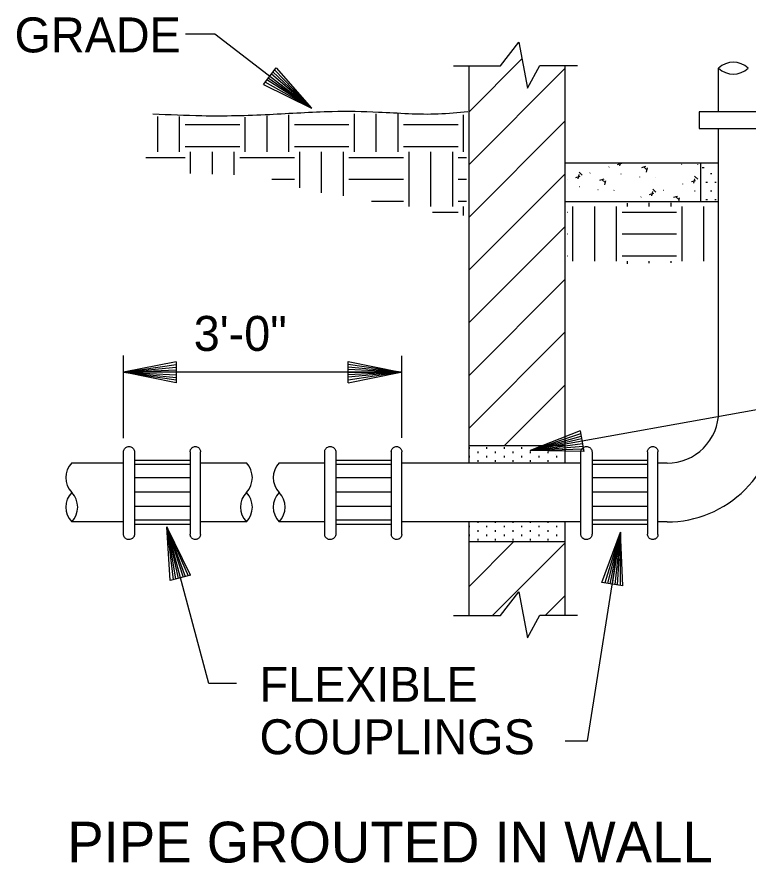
# Model space of a CAD drawing. Extents: x 9999.96 to 10005.26, y 9999.88 to 10002.38.
# Drawn here: x 10000.7094 to 10000.9186, y 10000.3471 to 10000.5891 of the extents above; entities that cross this region are included whole.
import ezdxf

# ---------------------------------------------------------------- set-up
doc = ezdxf.new("R2010")
doc.units = 0
doc.layers.add('Level 2', color=7, linetype='Continuous')

msp = doc.modelspace()

# ---------------------------------------------------------------- linework, layer by layer
at = {"layer": 'Level 2'}
for p, q in [((10000.83873, 10000.56198), (10000.85386, 10000.57711)), ((10000.77992, 10000.56982), (10000.78359, 10000.5746)), ((10000.78359, 10000.5746), (10000.79369, 10000.56304)), ((10000.83873, 10000.46147), (10000.83873, 10000.57519)), ((10000.86617, 10000.57519), (10000.86617, 10000.46147)), ((10000.78172, 10000.5722), (10000.79369, 10000.56304)), ((10000.79369, 10000.56304), (10000.78219, 10000.57279)), ((10000.79369, 10000.56304), (10000.78264, 10000.57339)), ((10000.79369, 10000.56304), (10000.78308, 10000.57396)), ((10000.83874, 10000.5469), (10000.86617, 10000.57433)), ((10000.91013, 10000.562), (10000.91013, 10000.57445)), ((10000.77992, 10000.56982), (10000.79369, 10000.56304)), ((10000.79369, 10000.56304), (10000.78039, 10000.57044)), ((10000.79369, 10000.56304), (10000.78088, 10000.57111)), ((10000.79369, 10000.56304), (10000.7813, 10000.57164)), ((10000.74969, 10000.55049), (10000.74969, 10000.56063)), ((10000.75594, 10000.55049), (10000.75594, 10000.56063)), ((10000.77469, 10000.55049), (10000.77469, 10000.56046)), ((10000.78094, 10000.55049), (10000.78094, 10000.56078)), ((10000.78719, 10000.55049), (10000.78719, 10000.56109)), ((10000.80594, 10000.55049), (10000.80594, 10000.5614)), ((10000.81219, 10000.55049), (10000.81219, 10000.56142)), ((10000.81844, 10000.55049), (10000.81844, 10000.56152)), ((10000.83719, 10000.55049), (10000.83719, 10000.56115)), ((10000.7575, 10000.5583), (10000.77313, 10000.5583)), ((10000.78875, 10000.5583), (10000.80438, 10000.5583)), ((10000.82, 10000.5583), (10000.83563, 10000.5583)), ((10000.83874, 10000.53181), (10000.86617, 10000.55925)), ((10000.91013, 10000.47621), (10000.91013, 10000.55723)), ((10000.7575, 10000.55205), (10000.77313, 10000.55205)), ((10000.75906, 10000.54436), (10000.75906, 10000.55049)), ((10000.76531, 10000.54418), (10000.76531, 10000.55049)), ((10000.77156, 10000.54398), (10000.77156, 10000.55049)), ((10000.78875, 10000.55205), (10000.80438, 10000.55205)), ((10000.79031, 10000.54022), (10000.79031, 10000.55049)), ((10000.79656, 10000.53875), (10000.79656, 10000.55049)), ((10000.80281, 10000.5379), (10000.80281, 10000.55049)), ((10000.82, 10000.55205), (10000.83563, 10000.55205)), ((10000.82156, 10000.53486), (10000.82156, 10000.55049)), ((10000.82781, 10000.53486), (10000.82781, 10000.55049)), ((10000.83406, 10000.53486), (10000.83406, 10000.55049)), ((10000.74622, 10000.54893), (10000.7575, 10000.54893)), ((10000.77313, 10000.54893), (10000.78875, 10000.54893)), ((10000.80438, 10000.54893), (10000.82, 10000.54893)), ((10000.83563, 10000.54893), (10000.838, 10000.54893)), ((10000.91017, 10000.54729), (10000.86617, 10000.54729)), ((10000.87876, 10000.54611), (10000.87878, 10000.54622)), ((10000.88124, 10000.54689), (10000.88244, 10000.54725)), ((10000.882, 10000.54729), (10000.88181, 10000.54648)), ((10000.88926, 10000.54631), (10000.88806, 10000.54595)), ((10000.8887, 10000.54624), (10000.8896, 10000.5454)), ((10000.88955, 10000.5447), (10000.88983, 10000.54592)), ((10000.89959, 10000.54694), (10000.89952, 10000.54701)), ((10000.90414, 10000.54689), (10000.90411, 10000.54678)), ((10000.90498, 10000.54729), (10000.90498, 10000.53632)), ((10000.90543, 10000.54608), (10000.90597, 10000.54608)), ((10000.83874, 10000.51674), (10000.86617, 10000.54417)), ((10000.86929, 10000.54323), (10000.87048, 10000.54359)), ((10000.87013, 10000.54404), (10000.86984, 10000.54283)), ((10000.8711, 10000.54389), (10000.8702, 10000.54473)), ((10000.87327, 10000.54445), (10000.8734, 10000.54448)), ((10000.88228, 10000.54418), (10000.88219, 10000.54415)), ((10000.88764, 10000.54328), (10000.88756, 10000.54335)), ((10000.89218, 10000.54323), (10000.89216, 10000.54314)), ((10000.90417, 10000.54268), (10000.90325, 10000.54353)), ((10000.90777, 10000.54436), (10000.90819, 10000.54436)), ((10000.78233, 10000.54268), (10000.78875, 10000.54268)), ((10000.80438, 10000.54268), (10000.82, 10000.54268)), ((10000.83563, 10000.54268), (10000.838, 10000.54268)), ((10000.8668, 10000.54247), (10000.86682, 10000.54256)), ((10000.8773, 10000.54266), (10000.8761, 10000.54229)), ((10000.87674, 10000.54258), (10000.87765, 10000.54173)), ((10000.87759, 10000.54104), (10000.87788, 10000.54226)), ((10000.89988, 10000.54124), (10000.8999, 10000.54134)), ((10000.90234, 10000.542), (10000.90353, 10000.54236)), ((10000.9032, 10000.54282), (10000.90292, 10000.5416)), ((10000.90652, 10000.54186), (10000.90694, 10000.54186)), ((10000.90902, 10000.54186), (10000.90944, 10000.54186)), ((10000.87033, 10000.54052), (10000.87023, 10000.54049)), ((10000.87568, 10000.53961), (10000.8756, 10000.53969)), ((10000.88022, 10000.53958), (10000.8802, 10000.53948)), ((10000.89039, 10000.53834), (10000.89158, 10000.53872)), ((10000.89124, 10000.53918), (10000.89096, 10000.53796)), ((10000.89221, 10000.53902), (10000.89129, 10000.53986)), ((10000.89436, 10000.53956), (10000.89449, 10000.5396)), ((10000.90339, 10000.5393), (10000.90328, 10000.53927)), ((10000.90777, 10000.53936), (10000.90819, 10000.53936)), ((10000.81083, 10000.53643), (10000.82, 10000.53643)), ((10000.83563, 10000.53643), (10000.838, 10000.53643)), ((10000.86617, 10000.53631), (10000.91017, 10000.53631)), ((10000.88406, 10000.53486), (10000.88406, 10000.53583)), ((10000.88791, 10000.53759), (10000.88794, 10000.53769)), ((10000.89031, 10000.53486), (10000.89031, 10000.53589)), ((10000.89656, 10000.53486), (10000.89656, 10000.53594)), ((10000.89841, 10000.53778), (10000.89721, 10000.53742)), ((10000.89783, 10000.53772), (10000.89875, 10000.53686)), ((10000.89872, 10000.53624), (10000.89898, 10000.53739)), ((10000.90652, 10000.53686), (10000.90694, 10000.53686)), ((10000.90902, 10000.53686), (10000.90944, 10000.53686)), ((10000.83719, 10000.53231), (10000.83719, 10000.53486)), ((10000.86844, 10000.51924), (10000.86844, 10000.53486)), ((10000.87469, 10000.51924), (10000.87469, 10000.53486)), ((10000.88094, 10000.51924), (10000.88094, 10000.53486)), ((10000.89969, 10000.51924), (10000.89969, 10000.53486)), ((10000.90594, 10000.51924), (10000.90594, 10000.53486)), ((10000.82829, 10000.5333), (10000.83563, 10000.5333)), ((10000.86679, 10000.5333), (10000.86688, 10000.5333)), ((10000.8825, 10000.5333), (10000.89813, 10000.5333)), ((10000.83874, 10000.50166), (10000.86617, 10000.52908)), ((10000.86679, 10000.52705), (10000.86688, 10000.52705)), ((10000.8825, 10000.52705), (10000.89813, 10000.52705)), ((10000.86679, 10000.5208), (10000.86688, 10000.5208)), ((10000.8825, 10000.5208), (10000.89813, 10000.5208)), ((10000.88406, 10000.51848), (10000.88406, 10000.51924)), ((10000.89031, 10000.51865), (10000.89031, 10000.51924)), ((10000.89656, 10000.51881), (10000.89656, 10000.51924)), ((10000.83875, 10000.48657), (10000.86617, 10000.51399)), ((10000.83875, 10000.47149), (10000.86618, 10000.49891)), ((10000.7399, 10000.46858), (10000.7399, 10000.49228)), ((10000.75495, 10000.49048), (10000.7399, 10000.48748)), ((10000.75495, 10000.49048), (10000.75494, 10000.48446)), ((10000.80414, 10000.48448), (10000.80415, 10000.4905)), ((10000.80415, 10000.4905), (10000.81919, 10000.48748)), ((10000.81946, 10000.46869), (10000.81946, 10000.49218)), ((10000.7399, 10000.48748), (10000.75495, 10000.48972)), ((10000.7399, 10000.48748), (10000.75497, 10000.48888)), ((10000.7399, 10000.48748), (10000.75495, 10000.4882)), ((10000.75496, 10000.4875), (10000.7399, 10000.48748)), ((10000.81919, 10000.48748), (10000.7399, 10000.48748)), ((10000.75494, 10000.48446), (10000.7399, 10000.48748)), ((10000.7399, 10000.48748), (10000.75496, 10000.486)), ((10000.7399, 10000.48748), (10000.75495, 10000.48527)), ((10000.7399, 10000.48748), (10000.75495, 10000.48674)), ((10000.81919, 10000.48748), (10000.80411, 10000.48608)), ((10000.81919, 10000.48748), (10000.80413, 10000.48896)), ((10000.80413, 10000.48746), (10000.81919, 10000.48748)), ((10000.81919, 10000.48748), (10000.80414, 10000.48969)), ((10000.81919, 10000.48748), (10000.80414, 10000.48822)), ((10000.80414, 10000.48448), (10000.81919, 10000.48748)), ((10000.81919, 10000.48748), (10000.80414, 10000.48676)), ((10000.81919, 10000.48748), (10000.80414, 10000.48524)), ((10000.8488, 10000.46645), (10000.86618, 10000.48382)), ((10000.96418, 10000.48451), (10000.85626, 10000.46511)), ((10000.87055, 10000.47073), (10000.85626, 10000.46511)), ((10000.87055, 10000.47073), (10000.8716, 10000.4648)), ((10000.85626, 10000.46511), (10000.87069, 10000.46998)), ((10000.85626, 10000.46511), (10000.87085, 10000.46916)), ((10000.85626, 10000.46511), (10000.87095, 10000.46849)), ((10000.86617, 10000.46645), (10000.83875, 10000.46645)), ((10000.83884, 10000.46561), (10000.83884, 10000.46603)), ((10000.84384, 10000.46561), (10000.84384, 10000.46603)), ((10000.84884, 10000.46561), (10000.84884, 10000.46603)), ((10000.85384, 10000.46561), (10000.85384, 10000.46603)), ((10000.87108, 10000.4678), (10000.85626, 10000.46511)), ((10000.85626, 10000.46511), (10000.87121, 10000.46705)), ((10000.85626, 10000.46511), (10000.87135, 10000.46632)), ((10000.85626, 10000.46511), (10000.87147, 10000.4656)), ((10000.85884, 10000.46561), (10000.85884, 10000.46603)), ((10000.86384, 10000.46561), (10000.86384, 10000.46603)), ((10000.73985, 10000.44115), (10000.73985, 10000.46466)), ((10000.74304, 10000.46466), (10000.74304, 10000.44121)), ((10000.75894, 10000.46473), (10000.75894, 10000.44115)), ((10000.76192, 10000.44108), (10000.76192, 10000.46473)), ((10000.79743, 10000.44115), (10000.79743, 10000.46466)), ((10000.8006, 10000.46466), (10000.8006, 10000.44121)), ((10000.8165, 10000.46473), (10000.8165, 10000.44115)), ((10000.81948, 10000.44108), (10000.81948, 10000.46473)), ((10000.83884, 10000.46311), (10000.83884, 10000.46353)), ((10000.84134, 10000.46436), (10000.84134, 10000.46478)), ((10000.84384, 10000.46311), (10000.84384, 10000.46353)), ((10000.84634, 10000.46436), (10000.84634, 10000.46478)), ((10000.84884, 10000.46311), (10000.84884, 10000.46353)), ((10000.85134, 10000.46436), (10000.85134, 10000.46478)), ((10000.85384, 10000.46311), (10000.85384, 10000.46353)), ((10000.8716, 10000.4648), (10000.85626, 10000.46511)), ((10000.85634, 10000.46436), (10000.85634, 10000.46478)), ((10000.85884, 10000.46311), (10000.85884, 10000.46353)), ((10000.86134, 10000.46436), (10000.86134, 10000.46478)), ((10000.86343, 10000.46381), (10000.86343, 10000.46381)), ((10000.86384, 10000.46311), (10000.86384, 10000.46353)), ((10000.87074, 10000.44115), (10000.87074, 10000.46466)), ((10000.87392, 10000.46466), (10000.87392, 10000.44121)), ((10000.88981, 10000.46473), (10000.88981, 10000.44115)), ((10000.89279, 10000.44108), (10000.89279, 10000.46473)), ((10000.73985, 10000.46147), (10000.72507, 10000.46147)), ((10000.75894, 10000.46221), (10000.74304, 10000.46221)), ((10000.75894, 10000.46108), (10000.74304, 10000.46108)), ((10000.77504, 10000.46147), (10000.76192, 10000.46147)), ((10000.79743, 10000.46147), (10000.78442, 10000.46147)), ((10000.8165, 10000.46221), (10000.8006, 10000.46221)), ((10000.8165, 10000.46108), (10000.8006, 10000.46108)), ((10000.87076, 10000.46147), (10000.81948, 10000.46147)), ((10000.84134, 10000.46186), (10000.84134, 10000.46228)), ((10000.84634, 10000.46186), (10000.84634, 10000.46228)), ((10000.85134, 10000.46186), (10000.85134, 10000.46228)), ((10000.85634, 10000.46186), (10000.85634, 10000.46228)), ((10000.86134, 10000.46186), (10000.86134, 10000.46228)), ((10000.88981, 10000.46221), (10000.87392, 10000.46221)), ((10000.88981, 10000.46108), (10000.87392, 10000.46108)), ((10000.8954, 10000.46147), (10000.89281, 10000.46147)), ((10000.75894, 10000.45724), (10000.74304, 10000.45724)), ((10000.8165, 10000.45724), (10000.8006, 10000.45724)), ((10000.88981, 10000.45724), (10000.87392, 10000.45724)), ((10000.75894, 10000.4532), (10000.74304, 10000.4532)), ((10000.8165, 10000.4532), (10000.8006, 10000.4532)), ((10000.88981, 10000.4532), (10000.87392, 10000.4532)), ((10000.75894, 10000.44909), (10000.74304, 10000.44909)), ((10000.8165, 10000.44909), (10000.8006, 10000.44909)), ((10000.88981, 10000.44909), (10000.87392, 10000.44909)), ((10000.73985, 10000.44467), (10000.72507, 10000.44467)), ((10000.75894, 10000.44513), (10000.74304, 10000.44513)), ((10000.74304, 10000.44406), (10000.75894, 10000.44406)), ((10000.77504, 10000.44467), (10000.76192, 10000.44467)), ((10000.79743, 10000.44467), (10000.78442, 10000.44467)), ((10000.8165, 10000.44513), (10000.8006, 10000.44513)), ((10000.8006, 10000.44406), (10000.8165, 10000.44406)), ((10000.87076, 10000.44467), (10000.81948, 10000.44467)), ((10000.83873, 10000.41785), (10000.83873, 10000.44467)), ((10000.84134, 10000.44436), (10000.84134, 10000.4445)), ((10000.84634, 10000.44436), (10000.84634, 10000.44456)), ((10000.85134, 10000.44436), (10000.85134, 10000.44461)), ((10000.85634, 10000.44436), (10000.85634, 10000.44467)), ((10000.86134, 10000.44436), (10000.86134, 10000.44473)), ((10000.86617, 10000.44467), (10000.86617, 10000.41785)), ((10000.88981, 10000.44513), (10000.87392, 10000.44513)), ((10000.87392, 10000.44406), (10000.88981, 10000.44406)), ((10000.8954, 10000.44467), (10000.89281, 10000.44467)), ((10000.75622, 10000.42868), (10000.75231, 10000.44323)), ((10000.75327, 10000.42792), (10000.75231, 10000.44323)), ((10000.75909, 10000.42946), (10000.75231, 10000.44323)), ((10000.75231, 10000.44323), (10000.75476, 10000.42829)), ((10000.75231, 10000.44323), (10000.75754, 10000.42902)), ((10000.75231, 10000.44323), (10000.75406, 10000.42811)), ((10000.75231, 10000.44323), (10000.75548, 10000.42849)), ((10000.75231, 10000.44323), (10000.7569, 10000.42886)), ((10000.75231, 10000.44323), (10000.75835, 10000.42926)), ((10000.83884, 10000.44311), (10000.83884, 10000.44353)), ((10000.84134, 10000.44186), (10000.84134, 10000.44228)), ((10000.84384, 10000.44311), (10000.84384, 10000.44353)), ((10000.84634, 10000.44186), (10000.84634, 10000.44228)), ((10000.84884, 10000.44311), (10000.84884, 10000.44353)), ((10000.85134, 10000.44186), (10000.85134, 10000.44228)), ((10000.85384, 10000.44311), (10000.85384, 10000.44353)), ((10000.85634, 10000.44186), (10000.85634, 10000.44228)), ((10000.85884, 10000.44311), (10000.85884, 10000.44353)), ((10000.86134, 10000.44186), (10000.86134, 10000.44228)), ((10000.86384, 10000.44311), (10000.86384, 10000.44353)), ((10000.87677, 10000.42735), (10000.88211, 10000.44174)), ((10000.88211, 10000.44174), (10000.87758, 10000.42722)), ((10000.88211, 10000.44174), (10000.8783, 10000.42709)), ((10000.88211, 10000.44174), (10000.87903, 10000.42699)), ((10000.87978, 10000.42685), (10000.88211, 10000.44174)), ((10000.88211, 10000.44174), (10000.88048, 10000.42676)), ((10000.88211, 10000.44174), (10000.88114, 10000.42664)), ((10000.88211, 10000.44174), (10000.88197, 10000.42652)), ((10000.88273, 10000.4264), (10000.88211, 10000.44174)), ((10000.86617, 10000.43899), (10000.83872, 10000.43899)), ((10000.83874, 10000.42622), (10000.8515, 10000.43899)), ((10000.83884, 10000.44061), (10000.83884, 10000.44103)), ((10000.84134, 10000.43936), (10000.84134, 10000.43978)), ((10000.84384, 10000.44061), (10000.84384, 10000.44103)), ((10000.84634, 10000.43936), (10000.84634, 10000.43978)), ((10000.84884, 10000.44061), (10000.84884, 10000.44103)), ((10000.85134, 10000.43936), (10000.85134, 10000.43978)), ((10000.85384, 10000.44061), (10000.85384, 10000.44103)), ((10000.85634, 10000.43936), (10000.85634, 10000.43978)), ((10000.85884, 10000.44061), (10000.85884, 10000.44103)), ((10000.86134, 10000.43936), (10000.86134, 10000.43978)), ((10000.86384, 10000.44061), (10000.86384, 10000.44103)), ((10000.84556, 10000.41796), (10000.86617, 10000.43856)), ((10000.75909, 10000.42946), (10000.75327, 10000.42792)), ((10000.88273, 10000.4264), (10000.87677, 10000.42735)), ((10000.86063, 10000.41794), (10000.86617, 10000.42348))]:
    msp.add_line(p, q, dxfattribs=at)
for points in [[(10000.75764, 10000.58427), (10000.76603, 10000.58427), (10000.79369, 10000.56304)], [(10000.83429, 10000.57517), (10000.84777, 10000.57517), (10000.85295, 10000.58194), (10000.85546, 10000.56877), (10000.85897, 10000.57524), (10000.86978, 10000.57524)], [(10000.73985, 10000.46466), (10000.73988, 10000.46491), (10000.73994, 10000.46515), (10000.74003, 10000.46539), (10000.74017, 10000.46559), (10000.74032, 10000.46578), (10000.74051, 10000.46595), (10000.74073, 10000.46607), (10000.74096, 10000.46617), (10000.7412, 10000.46623), (10000.74145, 10000.46625), (10000.7417, 10000.46623), (10000.74194, 10000.46617), (10000.74217, 10000.46607), (10000.74239, 10000.46595), (10000.74257, 10000.46578), (10000.74273, 10000.46559), (10000.74286, 10000.46539), (10000.74296, 10000.46515), (10000.74302, 10000.46491), (10000.74304, 10000.46466)], [(10000.75894, 10000.46473), (10000.75895, 10000.46496), (10000.75901, 10000.46519), (10000.75909, 10000.46541), (10000.75922, 10000.4656), (10000.75938, 10000.46578), (10000.75955, 10000.46593), (10000.75975, 10000.46605), (10000.75996, 10000.46615), (10000.76019, 10000.4662), (10000.76043, 10000.46622), (10000.76066, 10000.4662), (10000.76089, 10000.46615), (10000.7611, 10000.46605), (10000.7613, 10000.46593), (10000.76148, 10000.46578), (10000.76163, 10000.4656), (10000.76175, 10000.46541), (10000.76184, 10000.46519), (10000.7619, 10000.46496), (10000.76192, 10000.46473)], [(10000.79743, 10000.46466), (10000.79744, 10000.46491), (10000.7975, 10000.46515), (10000.79759, 10000.46539), (10000.79773, 10000.46559), (10000.79789, 10000.46578), (10000.79807, 10000.46595), (10000.79829, 10000.46607), (10000.79852, 10000.46617), (10000.79876, 10000.46623), (10000.79901, 10000.46625), (10000.79926, 10000.46623), (10000.7995, 10000.46617), (10000.79973, 10000.46607), (10000.79995, 10000.46595), (10000.80014, 10000.46578), (10000.8003, 10000.46559), (10000.80043, 10000.46539), (10000.80052, 10000.46515), (10000.80058, 10000.46491), (10000.8006, 10000.46466)], [(10000.8165, 10000.46473), (10000.81651, 10000.46496), (10000.81657, 10000.46519), (10000.81666, 10000.46541), (10000.81678, 10000.4656), (10000.81694, 10000.46578), (10000.81711, 10000.46593), (10000.81731, 10000.46605), (10000.81753, 10000.46615), (10000.81775, 10000.4662), (10000.81799, 10000.46622), (10000.81822, 10000.4662), (10000.81845, 10000.46615), (10000.81867, 10000.46605), (10000.81886, 10000.46593), (10000.81904, 10000.46578), (10000.8192, 10000.4656), (10000.81931, 10000.46541), (10000.81941, 10000.46519), (10000.81946, 10000.46496), (10000.81948, 10000.46473)], [(10000.87074, 10000.46466), (10000.87076, 10000.46491), (10000.87081, 10000.46515), (10000.87091, 10000.46539), (10000.87104, 10000.46559), (10000.8712, 10000.46578), (10000.8714, 10000.46595), (10000.8716, 10000.46607), (10000.87183, 10000.46617), (10000.87207, 10000.46623), (10000.87232, 10000.46625), (10000.87257, 10000.46623), (10000.87281, 10000.46617), (10000.87304, 10000.46607), (10000.87326, 10000.46595), (10000.87345, 10000.46578), (10000.87361, 10000.46559), (10000.87374, 10000.46539), (10000.87383, 10000.46515), (10000.8739, 10000.46491), (10000.87392, 10000.46466)], [(10000.88981, 10000.46473), (10000.88983, 10000.46496), (10000.88989, 10000.46519), (10000.88997, 10000.46541), (10000.89009, 10000.4656), (10000.89025, 10000.46578), (10000.89043, 10000.46593), (10000.89063, 10000.46605), (10000.89084, 10000.46615), (10000.89107, 10000.4662), (10000.8913, 10000.46622), (10000.89153, 10000.4662), (10000.89176, 10000.46615), (10000.89198, 10000.46605), (10000.89218, 10000.46593), (10000.89235, 10000.46578), (10000.89251, 10000.4656), (10000.89263, 10000.46541), (10000.89272, 10000.46519), (10000.89277, 10000.46496), (10000.89279, 10000.46473)], [(10000.77221, 10000.39847), (10000.76425, 10000.39847), (10000.75231, 10000.44323)], [(10000.86621, 10000.38205), (10000.87267, 10000.38205), (10000.88211, 10000.44174)], [(10000.74304, 10000.44121), (10000.74302, 10000.44097), (10000.74297, 10000.44072), (10000.74288, 10000.44049), (10000.74275, 10000.44027), (10000.74259, 10000.44008), (10000.74241, 10000.43992), (10000.7422, 10000.43978), (10000.74197, 10000.43968), (10000.74173, 10000.43961), (10000.74148, 10000.43959), (10000.74123, 10000.4396), (10000.74099, 10000.43966), (10000.74076, 10000.43975), (10000.74054, 10000.43988), (10000.74034, 10000.44003), (10000.74018, 10000.44022), (10000.74004, 10000.44043), (10000.73995, 10000.44066), (10000.73989, 10000.4409), (10000.73985, 10000.44115)], [(10000.76192, 10000.44108), (10000.76189, 10000.44084), (10000.76183, 10000.44063), (10000.76174, 10000.44041), (10000.76161, 10000.44021), (10000.76146, 10000.44003), (10000.76127, 10000.43989), (10000.76107, 10000.43977), (10000.76085, 10000.43969), (10000.76063, 10000.43964), (10000.76039, 10000.43963), (10000.76016, 10000.43965), (10000.75993, 10000.43971), (10000.75972, 10000.4398), (10000.75952, 10000.43993), (10000.75934, 10000.44008), (10000.7592, 10000.44026), (10000.75908, 10000.44047), (10000.759, 10000.44069), (10000.75895, 10000.44092), (10000.75894, 10000.44115)], [(10000.8006, 10000.44121), (10000.80058, 10000.44097), (10000.80053, 10000.44072), (10000.80045, 10000.44049), (10000.80031, 10000.44027), (10000.80016, 10000.44008), (10000.79997, 10000.43992), (10000.79976, 10000.43978), (10000.79953, 10000.43968), (10000.79929, 10000.43961), (10000.79904, 10000.43959), (10000.79879, 10000.4396), (10000.79855, 10000.43966), (10000.79832, 10000.43975), (10000.7981, 10000.43988), (10000.79791, 10000.44003), (10000.79775, 10000.44022), (10000.79761, 10000.44043), (10000.79751, 10000.44066), (10000.79745, 10000.4409), (10000.79743, 10000.44115)], [(10000.81948, 10000.44108), (10000.81946, 10000.44084), (10000.8194, 10000.44063), (10000.8193, 10000.44041), (10000.81918, 10000.44021), (10000.81902, 10000.44003), (10000.81883, 10000.43989), (10000.81864, 10000.43977), (10000.81842, 10000.43969), (10000.81819, 10000.43964), (10000.81796, 10000.43963), (10000.81772, 10000.43965), (10000.8175, 10000.43971), (10000.81728, 10000.4398), (10000.81708, 10000.43993), (10000.81691, 10000.44008), (10000.81676, 10000.44026), (10000.81665, 10000.44047), (10000.81656, 10000.44069), (10000.81651, 10000.44092), (10000.8165, 10000.44115)], [(10000.87392, 10000.44121), (10000.8739, 10000.44097), (10000.87384, 10000.44072), (10000.87376, 10000.44049), (10000.87364, 10000.44027), (10000.87347, 10000.44008), (10000.87328, 10000.43992), (10000.87307, 10000.43978), (10000.87284, 10000.43968), (10000.8726, 10000.43961), (10000.87235, 10000.43959), (10000.8721, 10000.4396), (10000.87186, 10000.43966), (10000.87164, 10000.43975), (10000.87142, 10000.43988), (10000.87123, 10000.44003), (10000.87106, 10000.44022), (10000.87093, 10000.44043), (10000.87082, 10000.44066), (10000.87076, 10000.4409), (10000.87074, 10000.44115)], [(10000.89279, 10000.44108), (10000.89277, 10000.44084), (10000.89271, 10000.44063), (10000.89261, 10000.44041), (10000.89249, 10000.44021), (10000.89233, 10000.44003), (10000.89215, 10000.43989), (10000.89195, 10000.43977), (10000.89173, 10000.43969), (10000.8915, 10000.43964), (10000.89127, 10000.43963), (10000.89103, 10000.43965), (10000.89081, 10000.43971), (10000.89059, 10000.4398), (10000.8904, 10000.43993), (10000.89022, 10000.44008), (10000.89007, 10000.44026), (10000.88996, 10000.44047), (10000.88988, 10000.44069), (10000.88982, 10000.44092), (10000.88981, 10000.44115)], [(10000.83429, 10000.41786), (10000.84777, 10000.41786), (10000.85295, 10000.42464), (10000.85546, 10000.41147), (10000.85897, 10000.41794), (10000.86978, 10000.41794)]]:
    msp.add_lwpolyline(points, dxfattribs=at)
msp.add_lwpolyline([(10000.90455, 10000.562), (10000.90455, 10000.55723), (10000.93264, 10000.55723), (10000.93264, 10000.562)], close=True, dxfattribs=at)
for centre, radius, start, end in [((10000.91435, 10000.57008), 0.00607, 45.9775, 134.0212), ((10000.91435, 10000.57882), 0.00607, 225.9788, 314.0225), ((10000.8954, 10000.4762), 0.01473, 269.9827, 360), ((10000.8954, 10000.4762), 0.03154, 269.9817, 0), ((10000.72944, 10000.45732), 0.00607, 135.9788, 224.0225), ((10000.77067, 10000.45732), 0.00607, 315.9775, 44.0212), ((10000.78878, 10000.45732), 0.00607, 135.9788, 224.0225), ((10000.72944, 10000.44888), 0.00607, 135.9775, 224.0212), ((10000.7207, 10000.44888), 0.00607, 315.9788, 44.0225), ((10000.77941, 10000.44888), 0.00607, 135.9775, 224.0212), ((10000.77067, 10000.44888), 0.00607, 315.9788, 44.0225), ((10000.78878, 10000.44888), 0.00607, 135.9775, 224.0212), ((10000.78005, 10000.44888), 0.00607, 315.9788, 44.0225)]:
    msp.add_arc(centre, radius, start, end, dxfattribs=at)
msp.add_spline([(10000.83838, 10000.562), (10000.82993, 10000.56131), (10000.81284, 10000.56182), (10000.79955, 10000.562), (10000.7816, 10000.56114), (10000.76228, 10000.56079), (10000.7483, 10000.56131)], degree=3, dxfattribs=at)

# ---------------------------------------------------------------- texts
for s, height, p in [('GRADE', 0.01, (10000.70871, 10000.57897)), ('3\'-0"', 0.01, (10000.75997, 10000.49358)), ('FLEXIBLE', 0.01, (10000.77879, 10000.39319)), ('COUPLINGS', 0.01, (10000.77879, 10000.37819)), ('PIPE GROUTED IN WALL', 0.0116667, (10000.7238, 10000.34723))]:
    msp.add_text(s, height=height, dxfattribs=at).set_placement(p)

doc.saveas('drawing.dxf')
